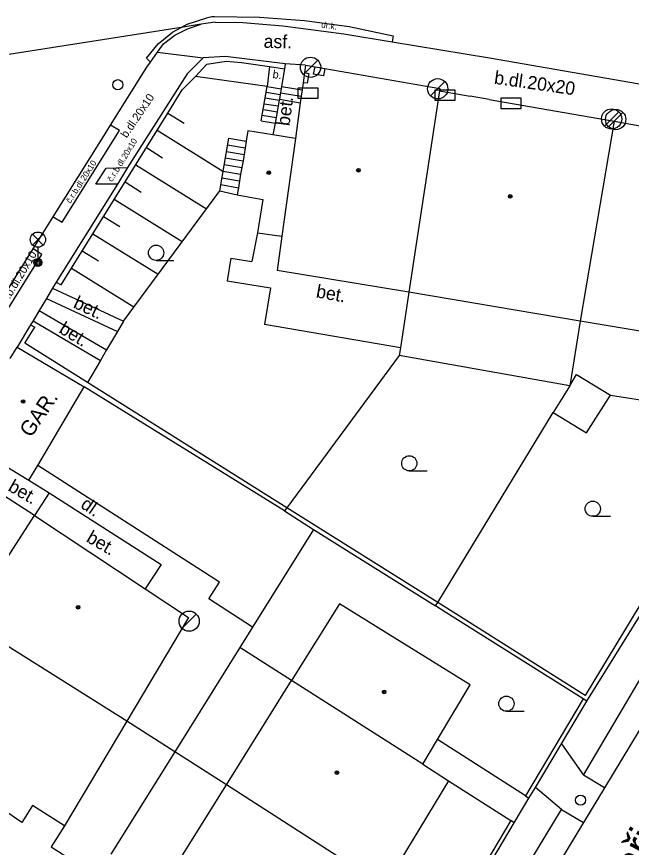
# Model space of a CAD drawing. Extents: x -595546 to -593986, y -1160845 to -1159202.
# Drawn here: x -594798.71 to -594768.38, y -1160812.74 to -1160771.75 of the extents above; entities that cross this region are included whole.
import ezdxf

# ---------------------------------------------------------------- set-up
doc = ezdxf.new("R2010")
doc.units = 0
for name, color, linetype in [('Level 24', 7, 'Continuous'), ('Level 27', 7, 'Continuous'), ('Level 28', 7, 'Continuous'), ('Level 31', 7, 'Continuous'), ('Level 33', 7, 'Continuous'), ('Level 36', 7, 'Continuous'), ('Level 39', 7, 'Continuous'), ('Nazvy ulic', 7, 'Continuous'), ('plynovod - povrch.  znaky - PRIS skut. velikost', 7, 'Continuous'), ('silnoproud - povrch.  znaky a  RIS  skut. velikost', 7, 'Continuous'), ('Specificka linie pasportu komunikaci', 7, 'Continuous'), ('TM - budovy zdene_ betonove - VP', 7, 'Continuous'), ('TM - chodniky - VP', 7, 'Continuous'), ('TM - dolni hrana svahu', 7, 'Continuous'), ('TM - komunikace - VP', 7, 'Continuous'), ('TM - plot drateny_ kovovy - VP', 7, 'Continuous'), ('TM - plot dreveny - VP', 7, 'Continuous'), ('TM - podezdivka plotu - VP', 7, 'Continuous'), ('TM - pomocna konstrukcni linie', 7, 'Continuous'), ('TM - popis objektu', 7, 'Continuous'), ('TM - popis povrchu', 7, 'Continuous'), ('TM - rozhrani mezi zpev. plochami mezi sebou - VP', 7, 'Continuous'), ('TM - rozhrani ploch obecne - VP', 7, 'Continuous'), ('TM - schody - VP', 7, 'Continuous'), ('TM - srafovani', 7, 'Continuous'), ('TM - vjezd na pozemek', 7, 'Continuous'), ('TM - vstup do budovy - zdene_ betonove', 7, 'Continuous')]:
    doc.layers.add(name, color=color, linetype=linetype)

msp = doc.modelspace()

# ---------------------------------------------------------------- linework, layer by layer
at = {"layer": 'Level 24'}
for points in [[(-594784.837, -1160775.778), (-594783.837, -1160775.778), (-594783.837, -1160775.278), (-594784.837, -1160775.278)], [(-594778.077, -1160775.878), (-594777.077, -1160775.878), (-594777.077, -1160775.378), (-594778.077, -1160775.378)], [(-594774.828, -1160776.279), (-594773.828, -1160776.279), (-594773.828, -1160775.779), (-594774.828, -1160775.779)]]:
    msp.add_lwpolyline(points, close=True, dxfattribs=at)
at = {"layer": 'Level 27'}
for p, q in [((-594784.564, -1160774.603), (-594783.857, -1160773.896)), ((-594778.294, -1160775.663), (-594777.587, -1160774.956)), ((-594769.714, -1160777.153), (-594769.007, -1160776.446)), ((-594769.514, -1160777.183), (-594768.807, -1160776.476)), ((-594790.554, -1160801.933), (-594789.847, -1160801.226))]:
    msp.add_line(p, q, dxfattribs=at)
for centre in [(-594784.21, -1160774.25), (-594777.94, -1160775.31), (-594769.36, -1160776.8), (-594769.16, -1160776.83), (-594790.2, -1160801.58)]:
    msp.add_circle(centre, 0.5, dxfattribs=at)
at = {"layer": 'Level 28'}
msp.add_circle((-594770.89, -1160810.41), 0.25, dxfattribs=at)
at = {"layer": 'Level 31'}
msp.add_circle((-594793.72, -1160775.11), 0.25, dxfattribs=at)
at = {"layer": 'Level 33'}
for p, q in [((-594797.925, -1160783.02), (-594797.395, -1160782.49)), ((-594797.925, -1160782.49), (-594797.395, -1160783.02)), ((-594797.66, -1160783.13), (-594797.66, -1160783.88))]:
    msp.add_line(p, q, dxfattribs=at)
for centre, radius in [((-594797.66, -1160782.755), 0.375), ((-594797.66, -1160783.88), 0.2), ((-594797.66, -1160783.88), 0.145), ((-594797.66, -1160783.88), 0.0876)]:
    msp.add_circle(centre, radius, dxfattribs=at)
at = {"layer": 'Level 36'}
for p, q in [((-594791.83, -1160783.775), (-594790.955, -1160783.775)), ((-594779.34, -1160794.165), (-594778.465, -1160794.165)), ((-594770.29, -1160796.405), (-594769.415, -1160796.405)), ((-594774.55, -1160806.025), (-594773.675, -1160806.025))]:
    msp.add_line(p, q, dxfattribs=at)
for centre in [(-594791.83, -1160783.4), (-594779.34, -1160793.79), (-594770.29, -1160796.03), (-594774.55, -1160805.65)]:
    msp.add_circle(centre, 0.375, dxfattribs=at)
at = {"layer": 'Level 39'}
for centre, radius in [((-594786.27, -1160779.45), 0.09), ((-594786.27, -1160779.45), 0.0398), ((-594781.85, -1160779.33), 0.09), ((-594781.85, -1160779.33), 0.0398), ((-594774.36, -1160780.62), 0.09), ((-594774.36, -1160780.62), 0.0398), ((-594798.39, -1160790.74), 0.09), ((-594798.39, -1160790.74), 0.0398), ((-594795.68, -1160800.89), 0.09), ((-594795.68, -1160800.89), 0.0398), ((-594780.58, -1160805.07), 0.09), ((-594780.58, -1160805.07), 0.0398), ((-594782.91, -1160809.05), 0.09), ((-594782.91, -1160809.05), 0.0398)]:
    msp.add_circle(centre, radius, dxfattribs=at)
at = {"layer": 'plynovod - povrch.  znaky - PRIS skut. velikost'}
for points in [[(-594784.07, -1160774.59), (-594783.99, -1160774.22)], [(-594783.51, -1160774.31), (-594783.57, -1160774.67)], [(-594783.57, -1160774.67), (-594784.07, -1160774.59)]]:
    msp.add_lwpolyline(points, dxfattribs=at)
at = {"layer": 'silnoproud - povrch.  znaky a  RIS  skut. velikost'}
for points in [[(-594784.51, -1160774.51), (-594784.29, -1160774.55)], [(-594784.29, -1160774.55), (-594784.37, -1160775.04)], [(-594784.37, -1160775.04), (-594784.58, -1160775.01)]]:
    msp.add_lwpolyline(points, dxfattribs=at)
at = {"layer": 'Specificka linie pasportu komunikaci'}
for points in [[(-594788.92, -1160772.02), (-594789.61, -1160772.13)], [(-594790.59, -1160772.28), (-594808.76, -1160775.13)], [(-594789.61, -1160772.13), (-594790.59, -1160772.28)]]:
    msp.add_lwpolyline(points, dxfattribs=at)
at = {"layer": 'TM - budovy zdene_ betonove - VP'}
for points in [[(-594784.46, -1160774.14), (-594784.51, -1160774.51)], [(-594784.46, -1160774.14), (-594783.99, -1160774.22)], [(-594783.99, -1160774.22), (-594783.51, -1160774.31)], [(-594783.51, -1160774.31), (-594777.83, -1160775.3)], [(-594784.51, -1160774.51), (-594784.58, -1160775.01)], [(-594784.58, -1160775.01), (-594784.63, -1160775.36)], [(-594777.83, -1160775.3), (-594777.85, -1160775.42)], [(-594784.63, -1160775.36), (-594784.67, -1160775.68), (-594784.72, -1160776)], [(-594777.85, -1160775.42), (-594779.37, -1160785.35)], [(-594777.85, -1160775.42), (-594776.34, -1160775.67)], [(-594784.72, -1160776), (-594784.96, -1160777.76)], [(-594775.4, -1160775.84), (-594769.24, -1160776.91)], [(-594769.24, -1160776.91), (-594770.91, -1160786.77)], [(-594769.24, -1160776.91), (-594762.84, -1160778.06)], [(-594787.3, -1160777.39), (-594787.38, -1160777.89)], [(-594786.07, -1160777.59), (-594787.3, -1160777.39)], [(-594784.96, -1160777.76), (-594786.07, -1160777.59)], [(-594784.96, -1160777.76), (-594785.63, -1160782.59)], [(-594787.38, -1160777.89), (-594787.44, -1160778.22), (-594787.49, -1160778.55), (-594787.54, -1160778.87), (-594787.6, -1160779.2), (-594787.66, -1160779.53), (-594787.71, -1160779.86), (-594787.77, -1160780.19), (-594787.83, -1160780.54)], [(-594787.83, -1160780.54), (-594786.57, -1160780.77)], [(-594786.57, -1160780.77), (-594786.83, -1160782.42)], [(-594786.83, -1160782.42), (-594785.63, -1160782.59)], [(-594785.63, -1160782.59), (-594785.86, -1160784.27)], [(-594779.37, -1160785.35), (-594785.86, -1160784.27)], [(-594770.91, -1160786.77), (-594779.37, -1160785.35)], [(-594764.78, -1160787.79), (-594770.91, -1160786.77)], [(-594799.03, -1160788.62), (-594798.69, -1160788.06)], [(-594798.69, -1160788.06), (-594795.37, -1160790.01)], [(-594797.67, -1160793.89), (-594795.37, -1160790.01)], [(-594801.43, -1160792.61), (-594798.1, -1160794.62)], [(-594798.1, -1160794.62), (-594797.67, -1160793.89)], [(-594801.07, -1160801.37), (-594801.05, -1160801.34), (-594800.73, -1160800.84), (-594797.83, -1160796.36)], [(-594797.83, -1160796.36), (-594792.37, -1160799.98)], [(-594792.37, -1160799.98), (-594790.23, -1160801.4)], [(-594782.78, -1160800.72), (-594785.15, -1160804.51)], [(-594780.05, -1160802.41), (-594782.78, -1160800.72)], [(-594793.28, -1160806.52), (-594801.18, -1160801.54)], [(-594790.23, -1160801.4), (-594793.28, -1160806.52)], [(-594776.33, -1160804.72), (-594780.05, -1160802.41)], [(-594788.36, -1160809.65), (-594785.15, -1160804.51)], [(-594778.68, -1160808.64), (-594785.15, -1160804.51)], [(-594777.95, -1160807.42), (-594776.33, -1160804.72)], [(-594793.28, -1160806.52), (-594796.35, -1160811.68)], [(-594778.68, -1160808.64), (-594777.95, -1160807.42)], [(-594778.68, -1160808.64), (-594777.41, -1160809.46)], [(-594791.52, -1160814.71), (-594788.36, -1160809.65)], [(-594780.57, -1160814.67), (-594788.36, -1160809.65)], [(-594777.41, -1160809.46), (-594780.57, -1160814.67)], [(-594798.46, -1160811.52), (-594799.68, -1160810.68)], [(-594797.92, -1160810.68), (-594798.46, -1160811.52)], [(-594796.35, -1160811.68), (-594797.92, -1160810.68)]]:
    msp.add_lwpolyline(points, dxfattribs=at)
at = {"layer": 'TM - chodniky - VP'}
for points in [[(-594770.75, -1160809.17), (-594766.14, -1160801.38)], [(-594769.71, -1160809.8), (-594770.75, -1160809.17)], [(-594781.26, -1160826.45), (-594771.83, -1160810.87)], [(-594771.83, -1160810.87), (-594770.75, -1160811.52)]]:
    msp.add_lwpolyline(points, dxfattribs=at)
at = {"layer": 'TM - dolni hrana svahu'}
msp.add_lwpolyline([(-594793.44, -1160786.77), (-594788.69, -1160780.35)], dxfattribs=at)
at = {"layer": 'TM - komunikace - VP'}
for points in [[(-594788.92, -1160772.02), (-594787.55, -1160772.04)], [(-594791.46, -1160773.09), (-594790.9, -1160772.67), (-594790.28, -1160772.35), (-594789.61, -1160772.13)], [(-594787.55, -1160772.04), (-594785.57, -1160772.21)], [(-594785.57, -1160772.21), (-594782.57, -1160772.6)], [(-594782.57, -1160772.6), (-594780.19, -1160772.99)], [(-594791.76, -1160773.51), (-594791.46, -1160773.09)], [(-594780.19, -1160772.99), (-594775.38, -1160773.78)], [(-594792.11, -1160774), (-594791.76, -1160773.51)], [(-594792.28, -1160774.24), (-594792.11, -1160774)], [(-594775.38, -1160773.78), (-594767.22, -1160775.19)], [(-594794.08, -1160777.1), (-594792.28, -1160774.24)], [(-594794.47, -1160777.74), (-594794.08, -1160777.1)], [(-594796.91, -1160781.63), (-594794.47, -1160777.74)], [(-594797.89, -1160783.2), (-594796.91, -1160781.63)], [(-594800.02, -1160786.6), (-594797.89, -1160783.2)], [(-594765.06, -1160802.1), (-594769.71, -1160809.8)], [(-594769.71, -1160809.8), (-594770.75, -1160811.52)], [(-594770.75, -1160811.52), (-594780.14, -1160827.04)]]:
    msp.add_lwpolyline(points, dxfattribs=at)
at = {"layer": 'TM - plot drateny_ kovovy - VP'}
for points in [[(-594789.89, -1160774.71), (-594789.33, -1160774.1), (-594788.38, -1160773.95), (-594787.61, -1160774.01)], [(-594787.61, -1160774.01), (-594786.23, -1160774.21)], [(-594786.23, -1160774.21), (-594785.49, -1160774.32)], [(-594790.54, -1160775.37), (-594789.89, -1160774.71)], [(-594796.52, -1160784.99), (-594796, -1160784.16), (-594791.25, -1160776.51), (-594790.54, -1160775.37)], [(-594798.3, -1160787.86), (-594797.81, -1160787.08)], [(-594795.21, -1160789.8), (-594798.3, -1160787.86)], [(-594785.38, -1160795.98), (-594795.21, -1160789.8)], [(-594763.8, -1160793.92), (-594770.66, -1160805.24)], [(-594777.94, -1160800.66), (-594785.38, -1160795.98)], [(-594770.66, -1160805.24), (-594777.94, -1160800.66)]]:
    msp.add_lwpolyline(points, dxfattribs=at)
at = {"layer": 'TM - plot dreveny - VP'}
for points in [[(-594770.76, -1160805.41), (-594773.6, -1160810.2)], [(-594774.33, -1160811.42), (-594777.45, -1160816.67)]]:
    msp.add_lwpolyline(points, dxfattribs=at)
at = {"layer": 'TM - podezdivka plotu - VP'}
for points in [[(-594789.5, -1160773.78), (-594790.3, -1160774.57)], [(-594788.4, -1160773.72), (-594789.5, -1160773.78)], [(-594785.47, -1160774.08), (-594788.4, -1160773.72)], [(-594785.47, -1160774.08), (-594785.49, -1160774.32)], [(-594790.3, -1160774.57), (-594790.68, -1160775.17)], [(-594790.68, -1160775.17), (-594793.24, -1160779.2)], [(-594793.24, -1160779.2), (-594793.74, -1160780.01)], [(-594793.74, -1160780.01), (-594796.76, -1160784.85)], [(-594796.76, -1160784.85), (-594796.52, -1160784.99)], [(-594798.02, -1160786.95), (-594798.69, -1160788.06)], [(-594798.02, -1160786.95), (-594797.81, -1160787.08)], [(-594785.5, -1160796.14), (-594795.37, -1160790.01)], [(-594785.5, -1160796.14), (-594784.06, -1160797.05)], [(-594784.06, -1160797.05), (-594778.05, -1160800.83)], [(-594770.59, -1160805.52), (-594767.45, -1160800.47)], [(-594777.54, -1160801.15), (-594778.05, -1160800.83)], [(-594770.76, -1160805.41), (-594777.54, -1160801.15)], [(-594771.84, -1160807.63), (-594770.59, -1160805.52)], [(-594770.59, -1160805.52), (-594770.76, -1160805.41)], [(-594773.12, -1160809.78), (-594771.84, -1160807.63)], [(-594773.44, -1160810.31), (-594773.12, -1160809.78)], [(-594773.6, -1160810.2), (-594773.44, -1160810.31)], [(-594777.28, -1160816.78), (-594774.16, -1160811.53)], [(-594774.16, -1160811.53), (-594774.33, -1160811.42)]]:
    msp.add_lwpolyline(points, dxfattribs=at)
at = {"layer": 'TM - pomocna konstrukcni linie'}
msp.add_lwpolyline([(-594780.13, -1160772.69), (-594780.19, -1160772.99)], dxfattribs=at)
at = {"layer": 'TM - rozhrani mezi zpev. plochami mezi sebou - VP'}
for points in [[(-594790.3, -1160772.13), (-594789.33, -1160771.81)], [(-594789.33, -1160771.81), (-594789.21, -1160771.77), (-594789.08, -1160771.75), (-594788.95, -1160771.75)], [(-594788.95, -1160771.75), (-594786.73, -1160771.77)], [(-594786.73, -1160771.77), (-594784.51, -1160771.94)], [(-594784.51, -1160771.94), (-594782.31, -1160772.24), (-594780.13, -1160772.69)], [(-594792.31, -1160773.8), (-594791.72, -1160773.1), (-594791.02, -1160772.51), (-594790.59, -1160772.28)], [(-594790.59, -1160772.28), (-594790.3, -1160772.13)], [(-594791.76, -1160773.51), (-594789.5, -1160773.78)], [(-594792.11, -1160774), (-594792.31, -1160773.8)], [(-594786.23, -1160774.21), (-594786.35, -1160775.19)], [(-594793.63, -1160777.37), (-594794.08, -1160777.1)], [(-594796.46, -1160781.9), (-594793.63, -1160777.37)], [(-594794.81, -1160780.02), (-594794.3, -1160779.22)], [(-594794.3, -1160779.22), (-594793.24, -1160779.2)], [(-594793.74, -1160780.01), (-594794.81, -1160780.02)], [(-594796.91, -1160781.63), (-594796.46, -1160781.9)], [(-594799.88, -1160787.36), (-594797.46, -1160783.48)], [(-594797.46, -1160783.48), (-594797.89, -1160783.2)], [(-594771.84, -1160807.63), (-594770.75, -1160809.17)], [(-594771.83, -1160810.87), (-594773.12, -1160809.78)]]:
    msp.add_lwpolyline(points, dxfattribs=at)
at = {"layer": 'TM - rozhrani ploch obecne - VP'}
for points in [[(-594785.49, -1160774.32), (-594785.64, -1160775.2)], [(-594786.35, -1160775.19), (-594789.89, -1160774.71)], [(-594786.64, -1160776.9), (-594786.35, -1160775.19)], [(-594786.35, -1160775.19), (-594785.66, -1160775.31)], [(-594785.66, -1160775.31), (-594785.7, -1160775.51), (-594785.71, -1160775.6), (-594785.75, -1160775.83)], [(-594785.64, -1160775.2), (-594785.66, -1160775.31)], [(-594785.64, -1160775.2), (-594784.63, -1160775.36)], [(-594785.75, -1160775.83), (-594785.76, -1160775.88), (-594785.81, -1160776.16), (-594785.86, -1160776.45), (-594785.91, -1160776.73), (-594785.96, -1160777.01)], [(-594785.75, -1160775.83), (-594784.72, -1160776)], [(-594786.64, -1160776.9), (-594785.96, -1160777.01)], [(-594785.96, -1160777.01), (-594786.07, -1160777.59)], [(-594788.69, -1160780.35), (-594788.25, -1160777.74)], [(-594788.25, -1160777.74), (-594787.38, -1160777.89)], [(-594788.69, -1160780.35), (-594787.83, -1160780.54)], [(-594786.83, -1160782.42), (-594787.11, -1160783.84)], [(-594788.14, -1160783.67), (-594788.33, -1160784.78)], [(-594788.14, -1160783.67), (-594787.11, -1160783.84)], [(-594796.94, -1160785.15), (-594793.44, -1160786.77)], [(-594788.33, -1160784.78), (-594786.18, -1160785.14)], [(-594786.18, -1160785.14), (-594786.48, -1160786.94)], [(-594779.37, -1160785.35), (-594779.78, -1160788.1)], [(-594797.24, -1160785.66), (-594793.74, -1160787.29)], [(-594797.6, -1160786.25), (-594794.27, -1160788.19)], [(-594797.9, -1160786.76), (-594794.57, -1160788.71)], [(-594793.44, -1160786.77), (-594793.74, -1160787.29)], [(-594770.91, -1160786.77), (-594771.42, -1160789.96)], [(-594779.78, -1160788.1), (-594786.48, -1160786.94)], [(-594793.74, -1160787.29), (-594794.27, -1160788.19)], [(-594794.27, -1160788.19), (-594794.57, -1160788.71)], [(-594779.78, -1160788.1), (-594779.84, -1160788.47)], [(-594794.57, -1160788.71), (-594795.21, -1160789.8)], [(-594779.84, -1160788.47), (-594785.38, -1160795.98)], [(-594771.42, -1160789.96), (-594779.84, -1160788.47)], [(-594771.42, -1160789.96), (-594771.09, -1160789.4), (-594769.42, -1160790.42)], [(-594771.42, -1160789.96), (-594772.24, -1160791.29)], [(-594770.6, -1160792.29), (-594769.42, -1160790.42)], [(-594769.42, -1160790.42), (-594767.1, -1160790.79)], [(-594777.94, -1160800.66), (-594772.24, -1160791.29)], [(-594772.24, -1160791.29), (-594770.6, -1160792.29)], [(-594787.08, -1160801.88), (-594789.23, -1160800.47), (-594788.7, -1160799.65), (-594797.67, -1160793.89)], [(-594798.1, -1160794.62), (-594797.11, -1160795.25)], [(-594797.83, -1160796.36), (-594799.65, -1160795.2)], [(-594797.11, -1160795.25), (-594797.83, -1160796.36)], [(-594797.11, -1160795.25), (-594791.58, -1160798.78), (-594792.37, -1160799.98)], [(-594785.38, -1160795.98), (-594785.5, -1160796.14)], [(-594784.06, -1160797.05), (-594787.08, -1160801.88)], [(-594778.05, -1160800.83), (-594777.94, -1160800.66)], [(-594787.08, -1160801.88), (-594787.7, -1160802.88)], [(-594787.7, -1160802.88), (-594790.91, -1160808.02)], [(-594785.15, -1160804.51), (-594787.7, -1160802.88)], [(-594790.91, -1160808.02), (-594793.28, -1160806.52)], [(-594773.6, -1160810.2), (-594777.95, -1160807.42)], [(-594790.91, -1160808.02), (-594794.06, -1160813.08)], [(-594788.36, -1160809.65), (-594790.91, -1160808.02)], [(-594777.41, -1160809.46), (-594774.33, -1160811.42)], [(-594796.35, -1160811.68), (-594797.01, -1160812.71), (-594794.74, -1160814.16)]]:
    msp.add_lwpolyline(points, dxfattribs=at)
at = {"layer": 'TM - schody - VP'}
for points in [[(-594786.4, -1160775.48), (-594785.71, -1160775.6)], [(-594785.7, -1160775.51), (-594784.67, -1160775.68)], [(-594786.5, -1160776.05), (-594785.81, -1160776.16)], [(-594786.45, -1160775.76), (-594785.76, -1160775.88)], [(-594786.54, -1160776.33), (-594785.86, -1160776.45)], [(-594786.59, -1160776.62), (-594785.91, -1160776.73)], [(-594788.31, -1160778.07), (-594787.44, -1160778.22)], [(-594788.36, -1160778.4), (-594787.49, -1160778.55)], [(-594788.42, -1160778.72), (-594787.54, -1160778.87)], [(-594788.53, -1160779.38), (-594787.66, -1160779.53)], [(-594788.47, -1160779.05), (-594787.6, -1160779.2)], [(-594788.58, -1160779.71), (-594787.71, -1160779.86)], [(-594788.64, -1160780.04), (-594787.77, -1160780.19)]]:
    msp.add_lwpolyline(points, dxfattribs=at)
at = {"layer": 'TM - srafovani'}
for points in [[(-594791.25, -1160776.51), (-594790.45, -1160777.01)], [(-594791.78, -1160777.36), (-594788.53, -1160779.38)], [(-594792.31, -1160778.21), (-594791.51, -1160778.71)], [(-594792.83, -1160779.06), (-594789.34, -1160781.23)], [(-594793.36, -1160779.91), (-594792.56, -1160780.41)], [(-594793.89, -1160780.76), (-594790.54, -1160782.84)], [(-594794.42, -1160781.61), (-594793.62, -1160782.11)], [(-594794.95, -1160782.46), (-594791.73, -1160784.46)], [(-594795.47, -1160783.31), (-594794.67, -1160783.8)], [(-594796, -1160784.16), (-594792.92, -1160786.07)]]:
    msp.add_lwpolyline(points, dxfattribs=at)
at = {"layer": 'TM - vjezd na pozemek'}
for points in [[(-594784.46, -1160774.14), (-594785.47, -1160774.08)], [(-594796.94, -1160785.15), (-594797.24, -1160785.66)], [(-594796.76, -1160784.85), (-594796.94, -1160785.15)], [(-594797.24, -1160785.66), (-594797.6, -1160786.25)], [(-594797.6, -1160786.25), (-594797.9, -1160786.76)], [(-594797.9, -1160786.76), (-594798.02, -1160786.95)], [(-594774.16, -1160811.53), (-594773.44, -1160810.31)]]:
    msp.add_lwpolyline(points, dxfattribs=at)
at = {"layer": 'TM - vstup do budovy - zdene_ betonove'}
msp.add_lwpolyline([(-594775.4, -1160775.84), (-594776.34, -1160775.67)], dxfattribs=at)

# ---------------------------------------------------------------- texts
at = {"layer": 'Nazvy ulic'}
msp.add_text('Vinařického', height=1.5, rotation=60.7576, dxfattribs=at).set_placement((-594769.5, -1160816.836))
at = {"layer": 'TM - popis objektu'}
msp.add_text('GAR.', height=0.75, rotation=56.01, dxfattribs=at).set_placement((-594798, -1160792.56))
at = {"layer": 'TM - popis povrchu'}
for s, height, rotation, p in [('dr.k.', 0.3, 351, (-594783.7, -1160772.28)), ('asf.', 0.65, 358.8788, (-594786.53, -1160773.29)), ('b.', 0.4, 352.5797, (-594786.1, -1160774.78)), ('b.dl.20x20', 0.65, 351.7788, (-594775.18, -1160775.06)), ('b.dl.20x10', 0.4, 55.9072, (-594793.28, -1160777.77)), ('bet.', 0.65, 82.7324, (-594785.25, -1160777.17)), ('č.r.b.dl.20x10', 0.3, 58.5968, (-594794, -1160779.93)), ('č.r.b.dl.20x10', 0.3, 57.3344, (-594796.05, -1160780.99)), ('č.r.b.dl.20x10', 0.4, 59, (-594799.35, -1160786.22)), ('bet.', 0.65, 349.837, (-594783.97, -1160785.6)), ('bet.', 0.65, 335.0496, (-594795.96, -1160786.09)), ('bet.', 0.65, 329.0876, (-594796.67, -1160787.32)), ('bet.', 0.65, 329.82, (-594799.18, -1160795.11)), ('dl.', 0.65, 325.3843, (-594795.6, -1160795.94)), ('bet.', 0.65, 329.82, (-594795.32, -1160797.63))]:
    msp.add_text(s, height=height, rotation=rotation, dxfattribs=at).set_placement(p)

doc.saveas('drawing.dxf')
